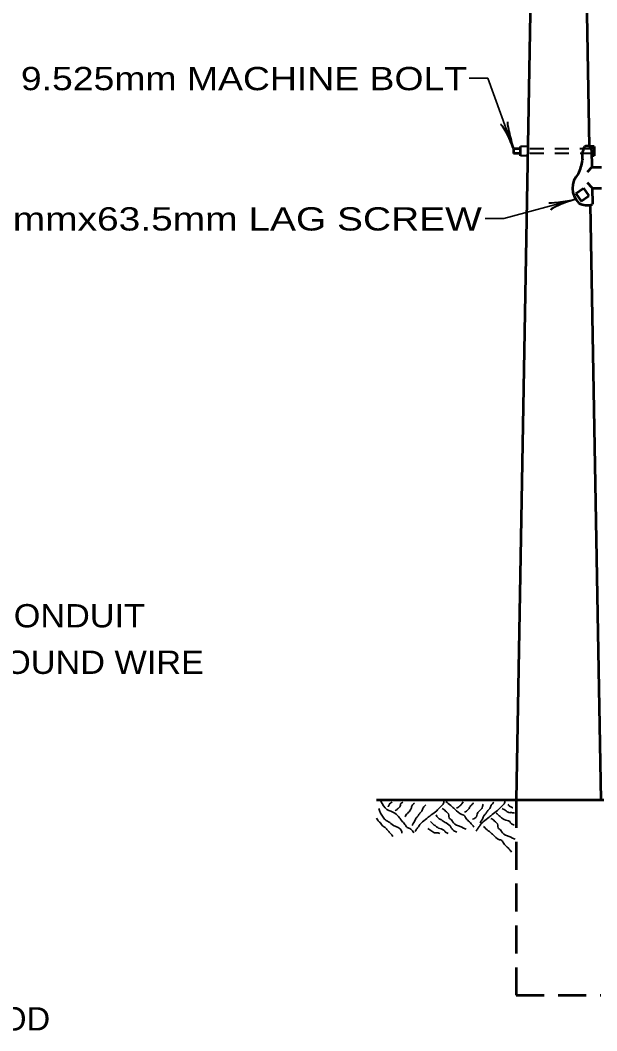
# Model space of a CAD drawing. Extents: x 14808 to 15663, y 10944 to 11488.
# Drawn here: x 15221.6 to 15295.9, y 11247.6 to 11377.9 of the extents above; entities that cross this region are included whole.
import ezdxf
from ezdxf.enums import TextEntityAlignment as Align

# ---------------------------------------------------------------- set-up
doc = ezdxf.new("R2010")
doc.units = 0
doc.header["$LTSCALE"] = 1.2
doc.linetypes.add('MEDIUM_DASHED', pattern=[4.5, 3, -1.5])
doc.linetypes.add('SHORT_DASHED', pattern=[2.7, 1.5, -1.2])
doc.layers.add('1', color=7, linetype='Continuous', lineweight=53)

msp = doc.modelspace()

# ---------------------------------------------------------------- linework, layer by layer
at = {"layer": '1'}
for p, q in [((15288.566, 11451.335), (15285.529, 11277.361)), ((15293.366, 11451.335), (15294.931, 11361.638)), ((15286.084, 11361.338), (15285.184, 11361.338)), ((15285.184, 11361.338), (15285.184, 11360.738)), ((15286.084, 11360.438), (15286.084, 11361.638)), ((15295.547, 11361.638), (15294.873, 11361.638)), ((15295.24, 11361.137), (15295.278, 11358.975)), ((15295.547, 11361.638), (15295.547, 11360.438)), ((15286.084, 11360.738), (15285.184, 11360.738)), ((15295.547, 11360.438), (15295.252, 11360.438)), ((15295.278, 11358.975), (15294.641, 11358.338)), ((15295.278, 11358.975), (15296.525, 11358.975)), ((15295.325, 11356.29), (15294.688, 11356.926)), ((15293.191, 11355.557), (15294.174, 11356.246)), ((15294.174, 11356.246), (15294.862, 11355.263)), ((15295.325, 11356.29), (15295.362, 11354.176)), ((15295.325, 11356.276), (15296.525, 11356.276)), ((15293.191, 11355.557), (15293.879, 11354.574)), ((15293.879, 11354.574), (15294.862, 11355.263)), ((15295.063, 11354.093), (15296.402, 11277.361)), ((15267.529, 11277.361), (15491.726, 11277.361))]:
    msp.add_line(p, q, dxfattribs=at)
at = {"layer": '1', "lineweight": 40}
for p, q in [((15286.995, 11361.638), (15286.084, 11361.638)), ((15286.984, 11360.438), (15286.084, 11360.438))]:
    msp.add_line(p, q, dxfattribs=at)
at = {"layer": '1', "linetype": 'SHORT_DASHED', "lineweight": 40}
for p, q in [((15295.536, 11361.338), (15286.995, 11361.338)), ((15295.547, 11360.738), (15286.984, 11360.738))]:
    msp.add_line(p, q, dxfattribs=at)
at = {"layer": '1', "linetype": 'MEDIUM_DASHED'}
for p, q in [((15285.529, 11277.361), (15285.529, 11252.161)), ((15285.529, 11252.161), (15296.402, 11252.161))]:
    msp.add_line(p, q, dxfattribs=at)
at = {"layer": '1', "lineweight": 35}
for points in [[(15285.14, 11361.411), (15281.857, 11370.432), (15279.457, 11370.432)], [(15293.173, 11354.827), (15283.9, 11352.342), (15281.5, 11352.342)]]:
    msp.add_lwpolyline(points, dxfattribs=at)
at = {"layer": '1'}
for centre, radius, start, end in [((15296.578, 11360.356), 2.582, 151.6071, 191.23066), ((15294.641, 11361.083), 0.602, 5.14198, 123.76222), ((15289.294, 11360.365), 4.779, 331.99837, 353.85569), ((15295.472, 11356.255), 2.705, 136.38146, 225.27926), ((15294.637, 11356.215), 2.164, 240.4205, 289.57853)]:
    msp.add_arc(centre, radius, start, end, dxfattribs=at)
at = {"layer": '1', "lineweight": 40}
for centre, major_axis, ratio, start_param, end_param in [((15284.919, 11362.761), (-0.523, 2.053), 0.07063, 6.2823074, 8.5597026), ((15284.381, 11362.528), (0.909, -1.95), 0.122415, 0.8963533, 3.1415927), ((15291.808, 11354.724), (-2.09, -0.342), 0.07063, 6.2823074, 8.5597026), ((15291.993, 11354.168), (2.021, 0.736), 0.122415, 0.8963533, 3.1415927)]:
    msp.add_ellipse(centre, major_axis=major_axis, ratio=ratio, start_param=start_param, end_param=end_param, dxfattribs=at)
at = {"layer": '1', "lineweight": 35}
for points in [[(15267.818, 11276.232), (15267.971, 11275.771), (15268.278, 11275.272), (15268.662, 11274.773), (15269.046, 11274.543), (15269.699, 11274.082), (15270.735, 11273.391), (15270.774, 11273.084)], [(15268.087, 11277.201), (15268.854, 11276.126), (15269.852, 11275.665), (15270.467, 11275.051), (15270.774, 11274.667), (15271.158, 11274.207), (15271.465, 11273.823), (15271.925, 11273.592), (15272.309, 11273.132)], [(15269.468, 11277.115), (15269.353, 11276.961), (15269.315, 11276.961), (15269.238, 11276.884), (15269.046, 11276.539), (15269.008, 11276.462)], [(15270.889, 11277.076), (15270.658, 11276.884), (15270.582, 11276.692), (15270.505, 11276.462), (15270.351, 11276.309), (15270.275, 11276.232), (15269.929, 11275.963)], [(15272.386, 11276.961), (15272.156, 11276.731), (15272.002, 11276.347), (15271.81, 11275.963), (15271.388, 11275.503), (15271.234, 11275.272), (15271.157, 11275.157)], [(15273.883, 11276.731), (15273.537, 11276.347), (15273.346, 11275.925), (15273.038, 11275.579), (15272.808, 11275.234), (15272.578, 11274.965), (15272.463, 11274.696), (15272.309, 11274.427), (15272.117, 11274.044)], [(15276.186, 11277.201), (15276.186, 11277.047), (15276.109, 11276.817), (15275.956, 11276.663), (15275.802, 11276.51), (15275.495, 11276.203), (15275.265, 11275.972), (15274.574, 11275.435), (15274.19, 11275.128), (15273.422, 11274.514), (15273.115, 11274.207), (15272.962, 11273.976), (15272.731, 11273.669), (15272.501, 11273.285)], [(15275.956, 11276.27), (15276.186, 11276.117), (15276.416, 11275.925), (15276.839, 11275.387), (15276.877, 11275.042), (15277.184, 11274.773), (15277.299, 11274.581), (15278.067, 11274.005), (15278.528, 11273.852), (15278.643, 11273.775), (15279.065, 11273.583)], [(15276.455, 11277.162), (15277.069, 11276.625), (15277.606, 11276.164), (15278.528, 11275.473), (15278.758, 11275.397), (15278.988, 11275.089), (15279.372, 11274.629), (15279.833, 11274.168), (15280.063, 11273.861)], [(15277.837, 11276.309), (15278.374, 11276.692), (15278.489, 11276.846), (15278.681, 11277.115)], [(15278.873, 11275.771), (15279.296, 11276.078), (15279.564, 11276.462), (15279.641, 11276.577), (15279.794, 11276.731), (15280.025, 11276.999)], [(15279.871, 11274.888), (15280.409, 11275.195), (15280.486, 11275.541), (15280.985, 11276.155), (15281.138, 11276.347), (15281.215, 11276.654), (15281.253, 11276.808)], [(15284.032, 11277.226), (15284.032, 11277.072), (15283.955, 11276.842), (15283.802, 11276.688), (15283.648, 11276.534), (15283.341, 11276.227), (15283.111, 11275.997), (15282.42, 11275.46), (15282.036, 11275.153), (15281.268, 11274.538), (15280.961, 11274.231), (15280.808, 11274.001), (15280.577, 11273.694), (15280.347, 11273.31)], [(15282.645, 11277.052), (15282.299, 11276.669), (15282.107, 11276.246), (15281.8, 11275.901), (15281.57, 11275.555), (15281.34, 11275.287), (15281.225, 11275.018), (15281.071, 11274.749), (15280.879, 11274.365)], [(15283.717, 11276.259), (15283.985, 11276.105), (15284.484, 11275.76), (15284.561, 11275.721), (15284.792, 11275.721), (15285.291, 11275.645)], [(15284.422, 11276.787), (15284.576, 11276.672), (15284.576, 11276.634), (15284.653, 11276.557), (15284.998, 11276.365), (15285.075, 11276.327)], [(15267.511, 11275.003), (15267.664, 11274.735), (15267.971, 11274.428), (15268.355, 11273.967), (15268.701, 11273.737), (15269.008, 11273.353), (15269.315, 11273.046), (15269.622, 11272.662)], [(15275.188, 11275.426), (15275.764, 11274.85), (15275.879, 11274.811), (15275.994, 11274.696), (15276.493, 11274.389), (15277.107, 11273.852), (15277.299, 11273.545), (15277.875, 11273.199)], [(15282.267, 11274.983), (15282.498, 11274.83), (15282.728, 11274.638), (15283.15, 11274.1), (15283.189, 11273.755), (15283.496, 11273.486), (15283.611, 11273.294), (15284.379, 11272.718), (15284.839, 11272.565), (15284.954, 11272.488), (15285.377, 11272.296)], [(15282.948, 11275.67), (15283.447, 11275.21), (15283.639, 11275.056), (15283.985, 11274.826), (15284.676, 11274.557), (15284.906, 11274.288), (15285.252, 11274.135)], [(15274.113, 11273.66), (15274.382, 11273.506), (15274.881, 11273.161), (15274.958, 11273.122), (15275.188, 11273.122), (15275.687, 11273.046)], [(15274.459, 11274.581), (15274.958, 11274.121), (15275.15, 11273.967), (15275.495, 11273.737), (15276.186, 11273.468), (15276.416, 11273.199), (15276.762, 11273.046)], [(15281.306, 11273.92), (15281.92, 11273.382), (15282.458, 11272.922), (15283.379, 11272.231), (15283.609, 11272.154), (15283.84, 11271.847), (15284.223, 11271.386), (15284.684, 11270.926), (15284.914, 11270.619)]]:
    msp.add_spline(points, degree=3, dxfattribs=at)

# ---------------------------------------------------------------- texts
at = {"layer": '1'}
for s, width, p in [('9.525mm MACHINE BOLT', 1.2, (15279.186, 11368.889)), ('9.525mmx63.5mm LAG SCREW', 1.25, (15281.087, 11350.792))]:
    msp.add_text(s, height=3, dxfattribs=dict(at, width=width)).set_placement(p, align=Align.RIGHT)
for s, width, p in [('STEEL CONDUIT', 1.1, (15202.362, 11299.612)), ('FOR GROUND WIRE', 1.1, (15202.362, 11293.612)), ('GROUND ROD', 1.05, (15196.196, 11247.628))]:
    msp.add_text(s, height=3, dxfattribs=dict(at, width=width)).set_placement(p)

doc.saveas('drawing.dxf')
